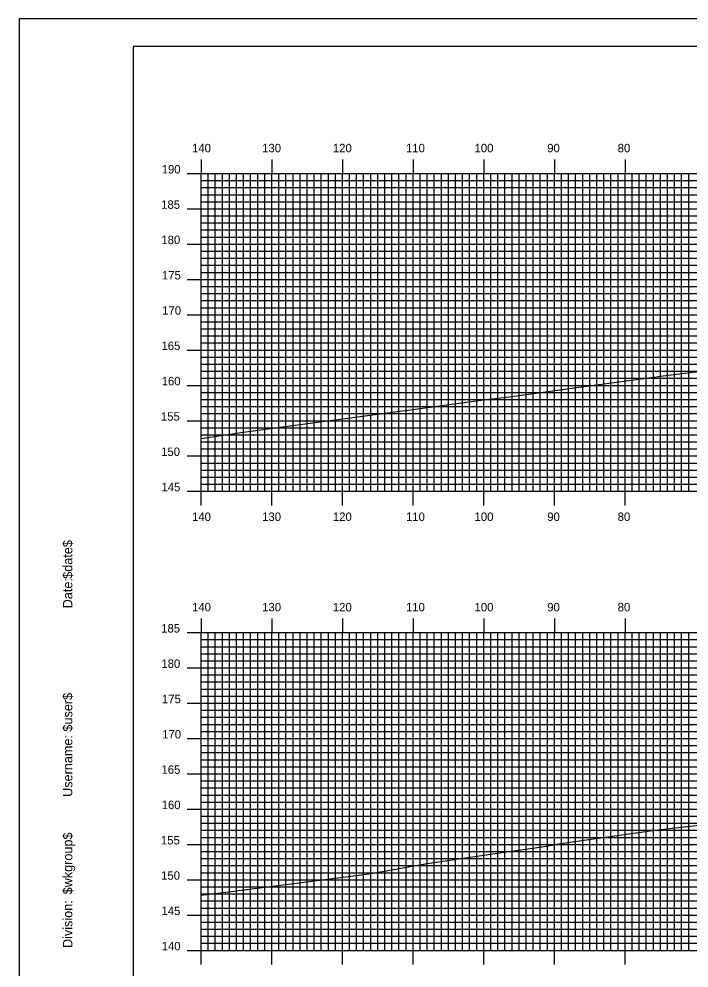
# Model space of a CAD drawing. Extents: x 1793666 to 1794009, y 442591 to 442811.
# Drawn here: x 1793665.5 to 1793760.4, y 442676.2 to 442810.5 of the extents above; entities that cross this region are included whole.
import ezdxf

# ---------------------------------------------------------------- set-up
doc = ezdxf.new("R2010")
doc.units = 0
for name, color, linetype in [('BORDER', 7, 'Continuous'), ('H_V ANNOTATION', 7, 'Continuous'), ('MAJOR', 7, 'Continuous'), ('MINOR', 7, 'Continuous'), ('PLOT BOUNDARY', 7, 'Continuous'), ('S_Roadway_Centerline', 7, 'Continuous')]:
    doc.layers.add(name, color=color, linetype=linetype)

msp = doc.modelspace()

# ---------------------------------------------------------------- linework, layer by layer
at = {"layer": 'BORDER'}
msp.add_lwpolyline([(1793681.71, 442596.67), (1794001.71, 442596.67), (1794001.71, 442806.67), (1793681.71, 442806.67)], close=True, dxfattribs=at)
at = {"layer": 'MAJOR'}
for p, q in [((1793691.31, 442790.67), (1793691.31, 442788.67)), ((1793701.31, 442790.67), (1793701.31, 442788.67)), ((1793711.31, 442790.67), (1793711.31, 442788.67)), ((1793721.31, 442790.67), (1793721.31, 442788.67)), ((1793731.31, 442790.67), (1793731.31, 442788.67)), ((1793741.31, 442790.67), (1793741.31, 442788.67)), ((1793751.31, 442790.67), (1793751.31, 442788.67)), ((1793689.31, 442788.67), (1793691.31, 442788.67)), ((1793691.31, 442788.67), (1793971.31, 442788.67)), ((1793691.31, 442743.67), (1793691.31, 442788.67)), ((1793691.31, 442743.67), (1793691.31, 442788.67)), ((1793691.31, 442788.67), (1793971.31, 442788.67)), ((1793701.31, 442743.67), (1793701.31, 442788.67)), ((1793711.31, 442743.67), (1793711.31, 442788.67)), ((1793721.31, 442743.67), (1793721.31, 442788.67)), ((1793731.31, 442743.67), (1793731.31, 442788.67)), ((1793741.31, 442743.67), (1793741.31, 442788.67)), ((1793751.31, 442743.67), (1793751.31, 442788.67)), ((1793689.31, 442783.67), (1793691.31, 442783.67)), ((1793691.31, 442783.67), (1793971.31, 442783.67)), ((1793689.31, 442778.67), (1793691.31, 442778.67)), ((1793691.31, 442778.67), (1793971.31, 442778.67)), ((1793689.31, 442773.67), (1793691.31, 442773.67)), ((1793691.31, 442773.67), (1793971.31, 442773.67)), ((1793689.31, 442768.67), (1793691.31, 442768.67)), ((1793691.31, 442768.67), (1793971.31, 442768.67)), ((1793689.31, 442763.67), (1793691.31, 442763.67)), ((1793691.31, 442763.67), (1793971.31, 442763.67)), ((1793689.31, 442758.67), (1793691.31, 442758.67)), ((1793691.31, 442758.67), (1793971.31, 442758.67)), ((1793689.31, 442753.67), (1793691.31, 442753.67)), ((1793691.31, 442753.67), (1793971.31, 442753.67)), ((1793689.31, 442748.67), (1793691.31, 442748.67)), ((1793691.31, 442748.67), (1793971.31, 442748.67)), ((1793689.31, 442743.67), (1793691.31, 442743.67)), ((1793691.31, 442743.67), (1793971.31, 442743.67)), ((1793691.31, 442743.67), (1793971.31, 442743.67)), ((1793691.31, 442741.66), (1793691.31, 442743.67)), ((1793701.31, 442741.66), (1793701.31, 442743.67)), ((1793711.31, 442741.66), (1793711.31, 442743.67)), ((1793721.31, 442741.66), (1793721.31, 442743.67)), ((1793731.31, 442741.66), (1793731.31, 442743.67)), ((1793741.31, 442741.66), (1793741.31, 442743.67)), ((1793751.31, 442741.66), (1793751.31, 442743.67)), ((1793691.31, 442725.67), (1793691.31, 442723.67)), ((1793701.31, 442725.67), (1793701.31, 442723.67)), ((1793711.31, 442725.67), (1793711.31, 442723.67)), ((1793721.31, 442725.67), (1793721.31, 442723.67)), ((1793731.31, 442725.67), (1793731.31, 442723.67)), ((1793741.31, 442725.67), (1793741.31, 442723.67)), ((1793751.31, 442725.67), (1793751.31, 442723.67)), ((1793689.31, 442723.67), (1793691.31, 442723.67)), ((1793691.31, 442723.67), (1793971.31, 442723.67)), ((1793691.31, 442678.67), (1793691.31, 442723.67)), ((1793691.31, 442678.67), (1793691.31, 442723.67)), ((1793691.31, 442723.67), (1793971.31, 442723.67)), ((1793701.31, 442678.67), (1793701.31, 442723.67)), ((1793711.31, 442678.67), (1793711.31, 442723.67)), ((1793721.31, 442678.67), (1793721.31, 442723.67)), ((1793731.31, 442678.67), (1793731.31, 442723.67)), ((1793741.31, 442678.67), (1793741.31, 442723.67)), ((1793751.31, 442678.67), (1793751.31, 442723.67)), ((1793689.31, 442718.67), (1793691.31, 442718.67)), ((1793691.31, 442718.67), (1793971.31, 442718.67)), ((1793689.31, 442713.67), (1793691.31, 442713.67)), ((1793691.31, 442713.67), (1793971.31, 442713.67)), ((1793689.31, 442708.67), (1793691.31, 442708.67)), ((1793691.31, 442708.67), (1793971.31, 442708.67)), ((1793689.31, 442703.67), (1793691.31, 442703.67)), ((1793691.31, 442703.67), (1793971.31, 442703.67)), ((1793689.31, 442698.67), (1793691.31, 442698.67)), ((1793691.31, 442698.67), (1793971.31, 442698.67)), ((1793689.31, 442693.67), (1793691.31, 442693.67)), ((1793691.31, 442693.67), (1793971.31, 442693.67)), ((1793689.31, 442688.67), (1793691.31, 442688.67)), ((1793691.31, 442688.67), (1793971.31, 442688.67)), ((1793689.31, 442683.67), (1793691.31, 442683.67)), ((1793691.31, 442683.67), (1793971.31, 442683.67)), ((1793689.31, 442678.67), (1793691.31, 442678.67)), ((1793691.31, 442678.67), (1793971.31, 442678.67)), ((1793691.31, 442678.67), (1793971.31, 442678.67)), ((1793691.31, 442676.66), (1793691.31, 442678.67)), ((1793701.31, 442676.66), (1793701.31, 442678.67)), ((1793711.31, 442676.66), (1793711.31, 442678.67)), ((1793721.31, 442676.66), (1793721.31, 442678.67)), ((1793731.31, 442676.66), (1793731.31, 442678.67)), ((1793741.31, 442676.66), (1793741.31, 442678.67)), ((1793751.31, 442676.66), (1793751.31, 442678.67))]:
    msp.add_line(p, q, dxfattribs=at)
at = {"layer": 'MINOR'}
for p, q in [((1793692.31, 442743.67), (1793692.31, 442788.67)), ((1793693.31, 442743.67), (1793693.31, 442788.67)), ((1793694.31, 442743.67), (1793694.31, 442788.67)), ((1793695.31, 442743.67), (1793695.31, 442788.67)), ((1793696.31, 442743.67), (1793696.31, 442788.67)), ((1793697.31, 442743.67), (1793697.31, 442788.67)), ((1793698.31, 442743.67), (1793698.31, 442788.67)), ((1793699.31, 442743.67), (1793699.31, 442788.67)), ((1793700.31, 442743.67), (1793700.31, 442788.67)), ((1793702.31, 442743.67), (1793702.31, 442788.67)), ((1793703.31, 442743.67), (1793703.31, 442788.67)), ((1793704.31, 442743.67), (1793704.31, 442788.67)), ((1793705.31, 442743.67), (1793705.31, 442788.67)), ((1793706.31, 442743.67), (1793706.31, 442788.67)), ((1793707.31, 442743.67), (1793707.31, 442788.67)), ((1793708.31, 442743.67), (1793708.31, 442788.67)), ((1793709.31, 442743.67), (1793709.31, 442788.67)), ((1793710.31, 442743.67), (1793710.31, 442788.67)), ((1793712.31, 442743.67), (1793712.31, 442788.67)), ((1793713.31, 442743.67), (1793713.31, 442788.67)), ((1793714.31, 442743.67), (1793714.31, 442788.67)), ((1793715.31, 442743.67), (1793715.31, 442788.67)), ((1793716.31, 442743.67), (1793716.31, 442788.67)), ((1793717.31, 442743.67), (1793717.31, 442788.67)), ((1793718.31, 442743.67), (1793718.31, 442788.67)), ((1793719.31, 442743.67), (1793719.31, 442788.67)), ((1793720.31, 442743.67), (1793720.31, 442788.67)), ((1793722.31, 442743.67), (1793722.31, 442788.67)), ((1793723.31, 442743.67), (1793723.31, 442788.67)), ((1793724.31, 442743.67), (1793724.31, 442788.67)), ((1793725.31, 442743.67), (1793725.31, 442788.67)), ((1793726.31, 442743.67), (1793726.31, 442788.67)), ((1793727.31, 442743.67), (1793727.31, 442788.67)), ((1793728.31, 442743.67), (1793728.31, 442788.67)), ((1793729.31, 442743.67), (1793729.31, 442788.67)), ((1793730.31, 442743.67), (1793730.31, 442788.67)), ((1793732.31, 442743.67), (1793732.31, 442788.67)), ((1793733.31, 442743.67), (1793733.31, 442788.67)), ((1793734.31, 442743.67), (1793734.31, 442788.67)), ((1793735.31, 442743.67), (1793735.31, 442788.67)), ((1793736.31, 442743.67), (1793736.31, 442788.67)), ((1793737.31, 442743.67), (1793737.31, 442788.67)), ((1793738.31, 442743.67), (1793738.31, 442788.67)), ((1793739.31, 442743.67), (1793739.31, 442788.67)), ((1793740.31, 442743.67), (1793740.31, 442788.67)), ((1793742.31, 442743.67), (1793742.31, 442788.67)), ((1793743.31, 442743.67), (1793743.31, 442788.67)), ((1793744.31, 442743.67), (1793744.31, 442788.67)), ((1793745.31, 442743.67), (1793745.31, 442788.67)), ((1793746.31, 442743.67), (1793746.31, 442788.67)), ((1793747.31, 442743.67), (1793747.31, 442788.67)), ((1793748.31, 442743.67), (1793748.31, 442788.67)), ((1793749.31, 442743.67), (1793749.31, 442788.67)), ((1793750.31, 442743.67), (1793750.31, 442788.67)), ((1793752.31, 442743.67), (1793752.31, 442788.67)), ((1793753.31, 442743.67), (1793753.31, 442788.67)), ((1793754.31, 442743.67), (1793754.31, 442788.67)), ((1793755.31, 442743.67), (1793755.31, 442788.67)), ((1793756.31, 442743.67), (1793756.31, 442788.67)), ((1793757.31, 442743.67), (1793757.31, 442788.67)), ((1793758.31, 442743.67), (1793758.31, 442788.67)), ((1793759.31, 442743.67), (1793759.31, 442788.67)), ((1793760.31, 442743.67), (1793760.31, 442788.67)), ((1793691.31, 442787.67), (1793971.31, 442787.67)), ((1793691.31, 442787.67), (1793693.32, 442787.67)), ((1793691.31, 442786.67), (1793971.31, 442786.67)), ((1793691.31, 442786.67), (1793693.32, 442786.67)), ((1793691.31, 442785.67), (1793971.31, 442785.67)), ((1793691.31, 442785.67), (1793693.32, 442785.67)), ((1793691.31, 442784.67), (1793971.31, 442784.67)), ((1793691.31, 442784.67), (1793693.32, 442784.67)), ((1793691.31, 442782.67), (1793971.31, 442782.67)), ((1793691.31, 442782.67), (1793693.32, 442782.67)), ((1793691.31, 442781.67), (1793971.31, 442781.67)), ((1793691.31, 442781.67), (1793693.32, 442781.67)), ((1793691.31, 442780.67), (1793971.31, 442780.67)), ((1793691.31, 442780.67), (1793693.32, 442780.67)), ((1793691.31, 442779.67), (1793971.31, 442779.67)), ((1793691.31, 442779.67), (1793693.32, 442779.67)), ((1793691.31, 442777.67), (1793971.31, 442777.67)), ((1793691.31, 442777.67), (1793693.32, 442777.67)), ((1793691.31, 442776.67), (1793971.31, 442776.67)), ((1793691.31, 442776.67), (1793693.32, 442776.67)), ((1793691.31, 442775.67), (1793971.31, 442775.67)), ((1793691.31, 442775.67), (1793693.32, 442775.67)), ((1793691.31, 442774.67), (1793971.31, 442774.67)), ((1793691.31, 442774.67), (1793693.32, 442774.67)), ((1793691.31, 442772.67), (1793971.31, 442772.67)), ((1793691.31, 442772.67), (1793693.32, 442772.67)), ((1793691.31, 442771.67), (1793971.31, 442771.67)), ((1793691.31, 442771.67), (1793693.32, 442771.67)), ((1793691.31, 442770.67), (1793971.31, 442770.67)), ((1793691.31, 442770.67), (1793693.32, 442770.67)), ((1793691.31, 442769.67), (1793971.31, 442769.67)), ((1793691.31, 442769.67), (1793693.32, 442769.67)), ((1793691.31, 442767.67), (1793971.31, 442767.67)), ((1793691.31, 442767.67), (1793693.32, 442767.67)), ((1793691.31, 442766.67), (1793971.31, 442766.67)), ((1793691.31, 442766.67), (1793693.32, 442766.67)), ((1793691.31, 442765.67), (1793971.31, 442765.67)), ((1793691.31, 442765.67), (1793693.32, 442765.67)), ((1793691.31, 442764.67), (1793971.31, 442764.67)), ((1793691.31, 442764.67), (1793693.32, 442764.67)), ((1793691.31, 442762.67), (1793971.31, 442762.67)), ((1793691.31, 442762.67), (1793693.32, 442762.67)), ((1793691.31, 442761.67), (1793971.31, 442761.67)), ((1793691.31, 442761.67), (1793693.32, 442761.67)), ((1793691.31, 442760.67), (1793971.31, 442760.67)), ((1793691.31, 442759.67), (1793971.31, 442759.67)), ((1793691.31, 442759.67), (1793693.32, 442759.67)), ((1793691.31, 442757.67), (1793971.31, 442757.67)), ((1793691.31, 442757.67), (1793693.32, 442757.67)), ((1793691.31, 442756.67), (1793971.31, 442756.67)), ((1793691.31, 442756.67), (1793693.32, 442756.67)), ((1793691.31, 442755.67), (1793971.31, 442755.67)), ((1793691.31, 442755.67), (1793693.32, 442755.67)), ((1793691.31, 442754.67), (1793971.31, 442754.67)), ((1793691.31, 442754.67), (1793693.32, 442754.67)), ((1793691.31, 442752.67), (1793971.31, 442752.67)), ((1793691.31, 442752.67), (1793693.32, 442752.67)), ((1793691.31, 442751.67), (1793971.31, 442751.67)), ((1793691.31, 442751.67), (1793693.32, 442751.67)), ((1793691.31, 442750.67), (1793971.31, 442750.67)), ((1793691.31, 442750.67), (1793693.32, 442750.67)), ((1793691.31, 442749.67), (1793971.31, 442749.67)), ((1793691.31, 442749.67), (1793693.32, 442749.67)), ((1793691.31, 442747.67), (1793971.31, 442747.67)), ((1793691.31, 442747.67), (1793693.32, 442747.67)), ((1793691.31, 442746.67), (1793971.31, 442746.67)), ((1793691.31, 442746.67), (1793693.32, 442746.67)), ((1793691.31, 442745.67), (1793971.31, 442745.67)), ((1793691.31, 442745.67), (1793693.32, 442745.67)), ((1793691.31, 442744.67), (1793971.31, 442744.67)), ((1793691.31, 442744.67), (1793693.32, 442744.67)), ((1793692.31, 442678.67), (1793692.31, 442723.67)), ((1793693.31, 442678.67), (1793693.31, 442723.67)), ((1793694.31, 442678.67), (1793694.31, 442723.67)), ((1793695.31, 442678.67), (1793695.31, 442723.67)), ((1793696.31, 442678.67), (1793696.31, 442723.67)), ((1793697.31, 442678.67), (1793697.31, 442723.67)), ((1793698.31, 442678.67), (1793698.31, 442723.67)), ((1793699.31, 442678.67), (1793699.31, 442723.67)), ((1793700.31, 442678.67), (1793700.31, 442723.67)), ((1793702.31, 442678.67), (1793702.31, 442723.67)), ((1793703.31, 442678.67), (1793703.31, 442723.67)), ((1793704.31, 442678.67), (1793704.31, 442723.67)), ((1793705.31, 442678.67), (1793705.31, 442723.67)), ((1793706.31, 442678.67), (1793706.31, 442723.67)), ((1793707.31, 442678.67), (1793707.31, 442723.67)), ((1793708.31, 442678.67), (1793708.31, 442723.67)), ((1793709.31, 442678.67), (1793709.31, 442723.67)), ((1793710.31, 442678.67), (1793710.31, 442723.67)), ((1793712.31, 442678.67), (1793712.31, 442723.67)), ((1793713.31, 442678.67), (1793713.31, 442723.67)), ((1793714.31, 442678.67), (1793714.31, 442723.67)), ((1793715.31, 442678.67), (1793715.31, 442723.67)), ((1793716.31, 442678.67), (1793716.31, 442723.67)), ((1793717.31, 442678.67), (1793717.31, 442723.67)), ((1793718.31, 442678.67), (1793718.31, 442723.67)), ((1793719.31, 442678.67), (1793719.31, 442723.67)), ((1793720.31, 442678.67), (1793720.31, 442723.67)), ((1793722.31, 442678.67), (1793722.31, 442723.67)), ((1793723.31, 442678.67), (1793723.31, 442723.67)), ((1793724.31, 442678.67), (1793724.31, 442723.67)), ((1793725.31, 442678.67), (1793725.31, 442723.67)), ((1793726.31, 442678.67), (1793726.31, 442723.67)), ((1793727.31, 442678.67), (1793727.31, 442723.67)), ((1793728.31, 442678.67), (1793728.31, 442723.67)), ((1793729.31, 442678.67), (1793729.31, 442723.67)), ((1793730.31, 442678.67), (1793730.31, 442723.67)), ((1793732.31, 442678.67), (1793732.31, 442723.67)), ((1793733.31, 442678.67), (1793733.31, 442723.67)), ((1793734.31, 442678.67), (1793734.31, 442723.67)), ((1793735.31, 442678.67), (1793735.31, 442723.67)), ((1793736.31, 442678.67), (1793736.31, 442723.67)), ((1793737.31, 442678.67), (1793737.31, 442723.67)), ((1793738.31, 442678.67), (1793738.31, 442723.67)), ((1793739.31, 442678.67), (1793739.31, 442723.67)), ((1793740.31, 442678.67), (1793740.31, 442723.67)), ((1793742.31, 442678.67), (1793742.31, 442723.67)), ((1793743.31, 442678.67), (1793743.31, 442723.67)), ((1793744.31, 442678.67), (1793744.31, 442723.67)), ((1793745.31, 442678.67), (1793745.31, 442723.67)), ((1793746.31, 442678.67), (1793746.31, 442723.67)), ((1793747.31, 442678.67), (1793747.31, 442723.67)), ((1793748.31, 442678.67), (1793748.31, 442723.67)), ((1793749.31, 442678.67), (1793749.31, 442723.67)), ((1793750.31, 442678.67), (1793750.31, 442723.67)), ((1793752.31, 442678.67), (1793752.31, 442723.67)), ((1793753.31, 442678.67), (1793753.31, 442723.67)), ((1793754.31, 442678.67), (1793754.31, 442723.67)), ((1793755.31, 442678.67), (1793755.31, 442723.67)), ((1793756.31, 442678.67), (1793756.31, 442723.67)), ((1793757.31, 442678.67), (1793757.31, 442723.67)), ((1793758.31, 442678.67), (1793758.31, 442723.67)), ((1793759.31, 442678.67), (1793759.31, 442723.67)), ((1793760.31, 442678.67), (1793760.31, 442723.67)), ((1793691.31, 442722.67), (1793971.31, 442722.67)), ((1793691.31, 442722.67), (1793693.32, 442722.67)), ((1793691.31, 442721.67), (1793971.31, 442721.67)), ((1793691.31, 442721.67), (1793693.32, 442721.67)), ((1793691.31, 442720.67), (1793971.31, 442720.67)), ((1793691.31, 442720.67), (1793693.32, 442720.67)), ((1793691.31, 442719.67), (1793971.31, 442719.67)), ((1793691.31, 442719.67), (1793693.32, 442719.67)), ((1793691.31, 442717.67), (1793971.31, 442717.67)), ((1793691.31, 442717.67), (1793693.32, 442717.67)), ((1793691.31, 442716.67), (1793971.31, 442716.67)), ((1793691.31, 442716.67), (1793693.32, 442716.67)), ((1793691.31, 442715.67), (1793971.31, 442715.67)), ((1793691.31, 442715.67), (1793693.32, 442715.67)), ((1793691.31, 442714.67), (1793971.31, 442714.67)), ((1793691.31, 442714.67), (1793693.32, 442714.67)), ((1793691.31, 442712.67), (1793971.31, 442712.67)), ((1793691.31, 442712.67), (1793693.32, 442712.67)), ((1793691.31, 442711.67), (1793971.31, 442711.67)), ((1793691.31, 442711.67), (1793693.32, 442711.67)), ((1793691.31, 442710.67), (1793971.31, 442710.67)), ((1793691.31, 442710.67), (1793693.32, 442710.67)), ((1793691.31, 442709.67), (1793971.31, 442709.67)), ((1793691.31, 442709.67), (1793693.32, 442709.67)), ((1793691.31, 442707.67), (1793971.31, 442707.67)), ((1793691.31, 442707.67), (1793693.32, 442707.67)), ((1793691.31, 442706.67), (1793971.31, 442706.67)), ((1793691.31, 442706.67), (1793693.32, 442706.67)), ((1793691.31, 442705.67), (1793971.31, 442705.67)), ((1793691.31, 442705.67), (1793693.32, 442705.67)), ((1793691.31, 442704.67), (1793971.31, 442704.67)), ((1793691.31, 442704.67), (1793693.32, 442704.67)), ((1793691.31, 442702.67), (1793971.31, 442702.67)), ((1793691.31, 442702.67), (1793693.32, 442702.67)), ((1793691.31, 442701.67), (1793971.31, 442701.67)), ((1793691.31, 442701.67), (1793693.32, 442701.67)), ((1793691.31, 442700.67), (1793971.31, 442700.67)), ((1793691.31, 442700.67), (1793693.32, 442700.67)), ((1793691.31, 442699.67), (1793971.31, 442699.67)), ((1793691.31, 442699.67), (1793693.32, 442699.67)), ((1793691.31, 442697.67), (1793971.31, 442697.67)), ((1793691.31, 442697.67), (1793693.32, 442697.67)), ((1793691.31, 442696.67), (1793971.31, 442696.67)), ((1793691.31, 442696.67), (1793693.32, 442696.67)), ((1793691.31, 442695.67), (1793971.31, 442695.67)), ((1793691.31, 442695.67), (1793693.32, 442695.67)), ((1793691.31, 442694.67), (1793971.31, 442694.67)), ((1793691.31, 442694.67), (1793693.32, 442694.67)), ((1793691.31, 442692.67), (1793971.31, 442692.67)), ((1793691.31, 442692.67), (1793693.32, 442692.67)), ((1793691.31, 442691.67), (1793971.31, 442691.67)), ((1793691.31, 442691.67), (1793693.32, 442691.67)), ((1793691.31, 442690.67), (1793971.31, 442690.67)), ((1793691.31, 442690.67), (1793693.32, 442690.67)), ((1793691.31, 442689.67), (1793971.31, 442689.67)), ((1793691.31, 442689.67), (1793693.32, 442689.67)), ((1793691.31, 442687.67), (1793971.31, 442687.67)), ((1793691.31, 442687.67), (1793693.32, 442687.67)), ((1793691.31, 442686.67), (1793971.31, 442686.67)), ((1793691.31, 442686.67), (1793693.32, 442686.67)), ((1793691.31, 442685.67), (1793971.31, 442685.67)), ((1793691.31, 442685.67), (1793693.32, 442685.67)), ((1793691.31, 442684.67), (1793971.31, 442684.67)), ((1793691.31, 442684.67), (1793693.32, 442684.67)), ((1793691.31, 442682.67), (1793971.31, 442682.67)), ((1793691.31, 442682.67), (1793693.32, 442682.67)), ((1793691.31, 442681.67), (1793971.31, 442681.67)), ((1793691.31, 442681.67), (1793693.32, 442681.67)), ((1793691.31, 442680.67), (1793971.31, 442680.67)), ((1793691.31, 442680.67), (1793693.32, 442680.67)), ((1793691.31, 442679.67), (1793971.31, 442679.67)), ((1793691.31, 442679.67), (1793693.32, 442679.67))]:
    msp.add_line(p, q, dxfattribs=at)
at = {"layer": 'PLOT BOUNDARY'}
msp.add_lwpolyline([(1793665.53, 442590.55), (1794005.53, 442590.55), (1794005.53, 442810.55), (1793665.53, 442810.55)], close=True, dxfattribs=at)
at = {"layer": 'S_Roadway_Centerline'}
for points in [[(1793691.31, 442751.17), (1793697.3, 442752.04), (1793703.19, 442752.86), (1793711.7, 442753.98), (1793724.04, 442755.61), (1793731.29, 442756.6), (1793734.94, 442757.05), (1793746.2, 442758.59), (1793752.56, 442759.46), (1793755.02, 442759.77), (1793757.39, 442760.1), (1793779.16, 442762.72)], [(1793691.31, 442686.49), (1793695.58, 442686.99), (1793715.11, 442689.51), (1793723.3, 442690.95), (1793732.59, 442692.34), (1793740.17, 442693.41), (1793742.16, 442693.8), (1793755.54, 442695.7), (1793774.28, 442697.83), (1793779.18, 442698.49), (1793797.37, 442700.87), (1793804.66, 442701.72), (1793813.07, 442702.76), (1793824.06, 442703.84), (1793825.68, 442704.01), (1793842.71, 442706), (1793859.75, 442706.42), (1793860.53, 442706.49), (1793861.29, 442706.54), (1793862.81, 442706.91)]]:
    msp.add_lwpolyline(points, dxfattribs=at)

# ---------------------------------------------------------------- texts
at = {"layer": 'BORDER'}
for s, p in [('$date$', (1793673.08, 442731.28)), ('Date:', (1793673.08, 442727.1)), ('$user$', (1793673.08, 442709.65)), ('Username:', (1793673.08, 442700.4)), ('$wkgroup$', (1793673.08, 442686.6)), ('Division:', (1793673.08, 442679))]:
    msp.add_text(s, height=1.339, rotation=90, dxfattribs=at).set_placement(p)
at = {"layer": 'H_V ANNOTATION'}
for s, p in [('140', (1793690.02, 442791.67)), ('130', (1793699.94, 442791.67)), ('120', (1793709.95, 442791.67)), ('110', (1793720.3, 442791.67)), ('100', (1793730, 442791.67)), ('90', (1793740.29, 442791.67)), ('80', (1793750.26, 442791.67)), ('190', (1793685.72, 442788.67)), ('185', (1793685.65, 442783.67)), ('180', (1793685.68, 442778.67)), ('175', (1793685.76, 442773.67)), ('170', (1793685.79, 442768.67)), ('165', (1793685.69, 442763.67)), ('160', (1793685.72, 442758.67)), ('155', (1793685.61, 442753.67)), ('150', (1793685.64, 442748.67)), ('145', (1793685.69, 442743.67)), ('140', (1793690.02, 442739.47)), ('130', (1793699.94, 442739.47)), ('120', (1793709.95, 442739.47)), ('110', (1793720.3, 442739.47)), ('100', (1793730, 442739.47)), ('90', (1793740.29, 442739.47)), ('80', (1793750.26, 442739.47)), ('140', (1793690.02, 442726.67)), ('130', (1793699.94, 442726.67)), ('120', (1793709.95, 442726.67)), ('110', (1793720.3, 442726.67)), ('100', (1793730, 442726.67)), ('90', (1793740.29, 442726.67)), ('80', (1793750.26, 442726.67)), ('185', (1793685.65, 442723.67)), ('180', (1793685.68, 442718.67)), ('175', (1793685.76, 442713.67)), ('170', (1793685.79, 442708.67)), ('165', (1793685.69, 442703.67)), ('160', (1793685.72, 442698.67)), ('155', (1793685.61, 442693.67)), ('150', (1793685.64, 442688.67)), ('145', (1793685.69, 442683.67)), ('140', (1793685.72, 442678.67))]:
    msp.add_text(s, height=1.2, dxfattribs=at).set_placement(p)
at = {"layer": 'MAJOR'}
for p in [(1793691.3, 442743.67), (1793691.3, 442678.67)]:
    msp.add_text('-', height=0.012, dxfattribs=at).set_placement(p)

doc.saveas('drawing.dxf')
